Omron CX-Programmer project NewProject (CX-Programmer 9.12)

# PLC NewPLC1: CP1L M
; 

## Global symbols (name address type ; comment)
A595 CHANNEL  ; IR00 Output For Background Execution (Rightmost Digits)
A596 CHANNEL  ; IR00 Output For Background Execution (Leftmost Digits)
A597 CHANNEL  ; DR00 Output For Background Execution
T0000 BOOL  ; Recipe Found Timer
ComparisonDataWord D10040 STRING[10]  ; Comparison Data Word
CurrentRecipe0 D11000 CHANNEL  ; Current Recipe 0
CurrentRecipe1 D11001 CHANNEL  ; Current Recipe 1
CurrentRecipe10 D11010 UINT  ; Current Recipe 10
CurrentRecipe11 D11011 UINT  ; Current Recipe 11
CurrentRecipe12 D11012 UINT  ; Current Recipe 12
CurrentRecipe13 D11013 UINT  ; Current Recipe 13
CurrentRecipe14 D11014 UINT  ; Current Recipe 14
CurrentRecipe15 D11015 UINT  ; Current Recipe 15
CurrentRecipe16 D11016 UINT  ; Current Recipe 16
CurrentRecipe17 D11017 UINT  ; Current Recipe 17
CurrentRecipe18 D11018 UINT  ; Current Recipe 18
CurrentRecipe19 D11019 UINT  ; Current Recipe 19
CurrentRecipe2 D11002 CHANNEL  ; Current Recipe 2
CurrentRecipe3 D11003 CHANNEL  ; Current Recipe 3
CurrentRecipe4 D11004 CHANNEL  ; Current Recipe 4
CurrentRecipe5 D11005 UINT  ; Current Recipe 5
CurrentRecipe6 D11006 UINT  ; Current Recipe 6
CurrentRecipe7 D11007 UINT  ; Current Recipe 7
CurrentRecipe8 D11008 UINT  ; Current Recipe 8
CurrentRecipe9 D11009 UINT  ; Current Recipe 9
ER_AER_FlagForBackgroundExecution A395.10 BOOL  ; $?St$Bk?_#[60] / ER/AER Flag For Background Execution / This flag is turned ON if an error or illegal access occurs during background execution.$?St$Bk?_#[60]
EqualsFlagForBackgroundExecution A598.01 BOOL  ; $?St$Bk?_#[61] / Equals Flag For Background Execution / Turns ON if matching data is found for an SRCH(181) instruction executed in the background.$?St$Bk?_#[61]
LoadRecipeButton W0.14 BOOL  ; Load Recipe Button
NextRecipe W0.13 BOOL  ; Next Recipe
PreviousRecipe W0.12 BOOL  ; Previous Recipe
RecipeFound W1.00 BOOL  ; Recipe Found
RecipeNotFound W1.01 BOOL  ; Recipe Not Found
RecipeNumber D10100 WORD  ; Recipe Number
RecipeNumberIndexPointer D10102 WORD  ; Recipe Number Index Pointer
RecipeView D11100 STRING[10]  ; Recipe View
SaveRecipeButton W0.15 BOOL  ; Save Recipe Button
SearchRecipes W0.00 BOOL  ; Search Recipes
SearchRecipesEnabled W0.02 BOOL  ; Search Recipes Enabled
SearchRecipesOneShot W0.01 BOOL  ; Search Recipes One Shot
SystemMemoryControlArea H0 CHANNEL  ; System Memory Control Area
SystemMemoryNotificationArea H100 CHANNEL  ; System Memory Notification Area

## Program NewProgram1 (cyclic task 0)

### Section LoadRecipes

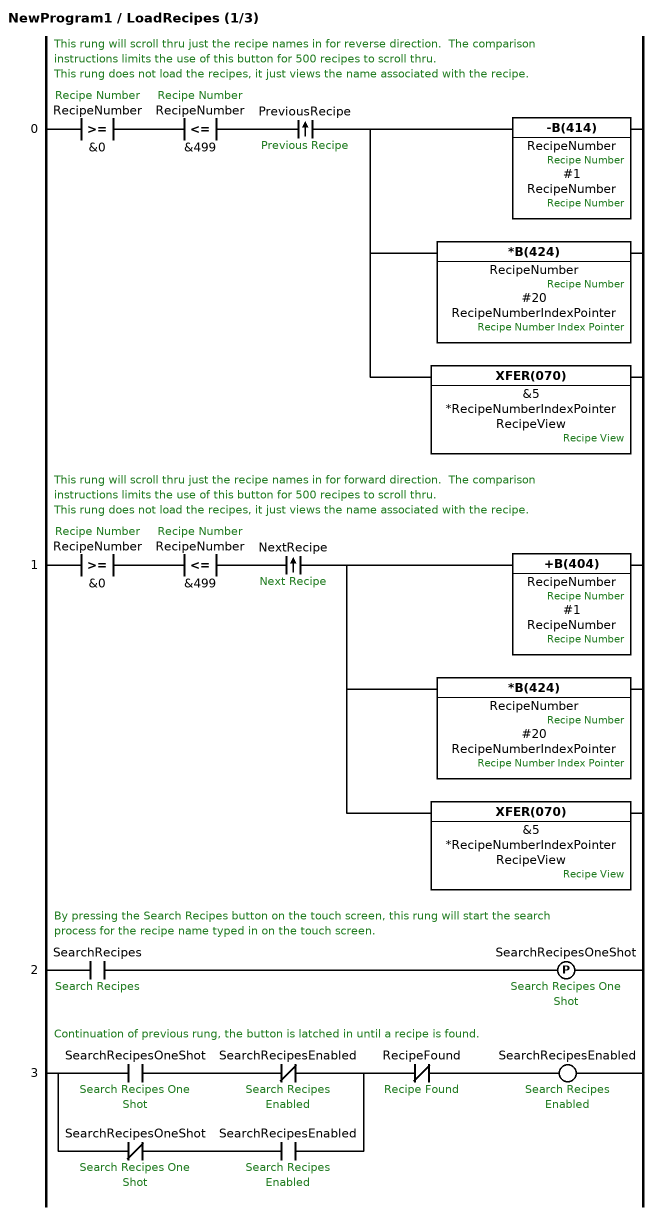
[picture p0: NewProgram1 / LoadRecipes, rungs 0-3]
; rung 0: This rung will scroll thru just the recipe names in for reverse direction.  The comparison instructions limits the use of this button for 500 recipes to scroll thru. / This rung does not load the recipes, it just views the name associated with the recipe.
LD>=(325) RecipeNumber &0  ; Recipe Number
AND<=(315) RecipeNumber &499  ; Recipe Number
@AND PreviousRecipe  ; Previous Recipe
-B(414) RecipeNumber #1 RecipeNumber  ; Recipe Number
*B(424) RecipeNumber #20 RecipeNumberIndexPointer  ; Recipe Number, Recipe Number Index Pointer
XFER(070) &5 *RecipeNumberIndexPointer RecipeView  ; Recipe View
; rung 1: This rung will scroll thru just the recipe names in for forward direction.  The comparison instructions limits the use of this button for 500 recipes to scroll thru. / This rung does not load the recipes, it just views the name associated with the recipe.
LD>=(325) RecipeNumber &0  ; Recipe Number
AND<=(315) RecipeNumber &499  ; Recipe Number
@AND NextRecipe  ; Next Recipe
+B(404) RecipeNumber #1 RecipeNumber  ; Recipe Number
*B(424) RecipeNumber #20 RecipeNumberIndexPointer  ; Recipe Number, Recipe Number Index Pointer
XFER(070) &5 *RecipeNumberIndexPointer RecipeView  ; Recipe View
; rung 2: By pressing the Search Recipes button on the touch screen, this rung will start the search process for the recipe name typed in on the touch screen.
LD SearchRecipes  ; Search Recipes
DIFU(013) SearchRecipesOneShot  ; Search Recipes One Shot
; rung 3: Continuation of previous rung, the button is latched in until a recipe is found.
LD SearchRecipesOneShot  ; Search Recipes One Shot
ANDNOT SearchRecipesEnabled  ; Search Recipes Enabled
LDNOT SearchRecipesOneShot  ; Search Recipes One Shot
AND SearchRecipesEnabled  ; Search Recipes Enabled
ORLD
ANDNOT RecipeFound  ; Recipe Found
OUT SearchRecipesEnabled  ; Search Recipes Enabled

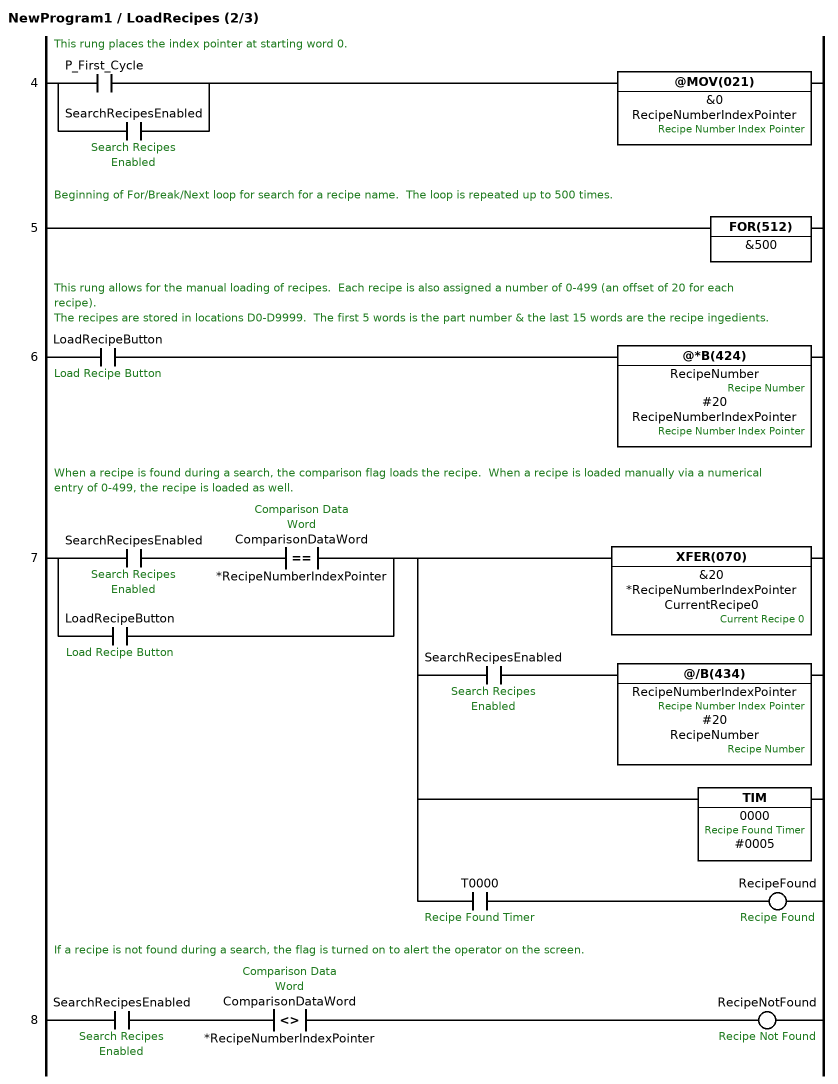
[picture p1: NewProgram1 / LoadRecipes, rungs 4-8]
; rung 4: This rung places the index pointer at starting word 0.
LD P_First_Cycle
OR SearchRecipesEnabled  ; Search Recipes Enabled
@MOV(021) &0 RecipeNumberIndexPointer  ; Recipe Number Index Pointer
; rung 5: Beginning of For/Break/Next loop for search for a recipe name.  The loop is repeated up to 500 times.
FOR(512) &500
; rung 6: This rung allows for the manual loading of recipes.  Each recipe is also assigned a number of 0-499 (an offset of 20 for each recipe). / The recipes are stored in locations D0-D9999.  The first 5 words is the part number & the last 15 words are the recipe ingedients.
LD LoadRecipeButton  ; Load Recipe Button
@*B(424) RecipeNumber #20 RecipeNumberIndexPointer  ; Recipe Number, Recipe Number Index Pointer
; rung 7: When a recipe is found during a search, the comparison flag loads the recipe.  When a recipe is loaded manually via a numerical entry of 0-499, the recipe is loaded as well.
LD SearchRecipesEnabled  ; Search Recipes Enabled
AND=$(670) ComparisonDataWord *RecipeNumberIndexPointer  ; Comparison Data Word
OR LoadRecipeButton  ; Load Recipe Button
OUT TR0
XFER(070) &20 *RecipeNumberIndexPointer CurrentRecipe0  ; Current Recipe 0
AND SearchRecipesEnabled  ; Search Recipes Enabled
@/B(434) RecipeNumberIndexPointer #20 RecipeNumber  ; Recipe Number Index Pointer, Recipe Number
LD TR0
TIM 0000 #0005  ; Recipe Found Timer
AND T0000  ; Recipe Found Timer
OUT RecipeFound  ; Recipe Found
; rung 8: If a recipe is not found during a search, the flag is turned on to alert the operator on the screen.
LD SearchRecipesEnabled  ; Search Recipes Enabled
AND<>$(671) ComparisonDataWord *RecipeNumberIndexPointer  ; Comparison Data Word
OUT RecipeNotFound  ; Recipe Not Found

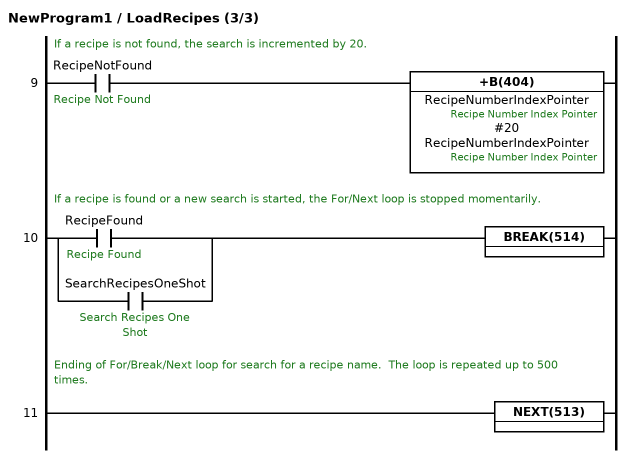
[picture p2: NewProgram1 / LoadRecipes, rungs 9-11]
; rung 9: If a recipe is not found, the search is incremented by 20.
LD RecipeNotFound  ; Recipe Not Found
+B(404) RecipeNumberIndexPointer #20 RecipeNumberIndexPointer  ; Recipe Number Index Pointer
; rung 10: If a recipe is found or a new search is started, the For/Next loop is stopped momentarily.
LD RecipeFound  ; Recipe Found
OR SearchRecipesOneShot  ; Search Recipes One Shot
BREAK(514)
; rung 11: Ending of For/Break/Next loop for search for a recipe name.  The loop is repeated up to 500 times.
NEXT(513)

### Section SaveRecipes

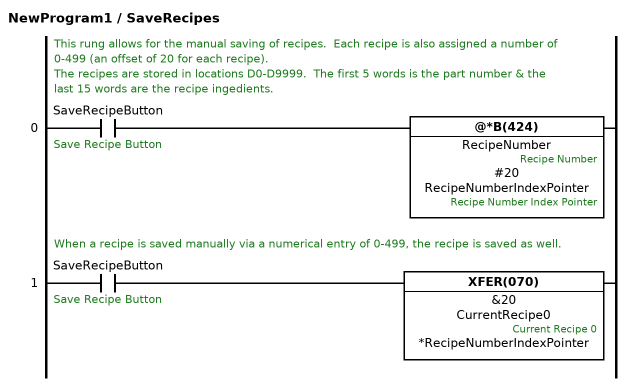
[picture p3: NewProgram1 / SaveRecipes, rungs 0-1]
; rung 0: This rung allows for the manual saving of recipes.  Each recipe is also assigned a number of 0-499 (an offset of 20 for each recipe). / The recipes are stored in locations D0-D9999.  The first 5 words is the part number & the last 15 words are the recipe ingedients.
LD SaveRecipeButton  ; Save Recipe Button
@*B(424) RecipeNumber #20 RecipeNumberIndexPointer  ; Recipe Number, Recipe Number Index Pointer
; rung 1: When a recipe is saved manually via a numerical entry of 0-499, the recipe is saved as well.
LD SaveRecipeButton  ; Save Recipe Button
XFER(070) &20 CurrentRecipe0 *RecipeNumberIndexPointer  ; Current Recipe 0

### Section END
; rung 0
END(001)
